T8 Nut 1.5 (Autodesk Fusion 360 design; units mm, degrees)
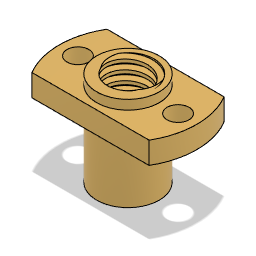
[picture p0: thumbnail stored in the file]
sketch "Sketch1" plane through (0, 0, 0) normal (0, 1, 0) x axis (1, 0, 0)
  line L1 (-11, -6) -> (11, -6)
  line L2 (-11, 6) -> (-11, -6)
  line L3 (11, 6) -> (-11, 6)
  line L4 (11, -6) -> (11, 6)
  line L5 (8, 0) -> (0, 0)
  circle C1 centre (0, 0) radius 4
  circle C2 centre (-8, 0) radius 1.75
  circle C3 centre (8, 0) radius 1.75
  arc A1 centre (0.7983, 0) radius 11.7983 clockwise from (-9.3604, -6) to (-11, 0)
  circle C4 centre (0, 0) radius 4
  arc A2 centre (-0.7983, 0) radius 11.7983 clockwise from (11, 0) to (9.3604, -6)
  arc A3 centre (0.7983, 0) radius 11.7983 clockwise from (-11, 0) to (-9.3604, 6)
  arc A4 centre (-0.7983, 0) radius 11.7983 clockwise from (9.3604, 6) to (11, 0)
  point P1 (0, 0)
  point P6 (0, 0)
  point P7 (0, 0)
  point P8 (0, 0)
  point P9 (8, 0)
  point P11 (8, 0)
  point P12 (-9.3604, -6)
  point P4 (-11, 6)
  point P5 (11, 6)
  point P3 (-11, -6)
  point P10 (-8, 0)
  horizontal L1
  perpendicular L1 L2
  parallel L1 L3
  parallel L2 L4
  coincident P1 P6
  coincident P6 P7
  coincident P1 P8
  horizontal L5
  coincident P9 P11
  tangent L2 A1
  coincident L1 P12
  dimension "d1" distance P4 P5 = 22
  dimension "d2" distance P3 P4 = 12
  dimension "d3" diameter C1 = 8
  dimension "d4" distance P8 P9 = 8
  dimension "d5" distance P9 P10 = 16
  dimension "d6" diameter C2 = 3.5
  dimension "d7" diameter C3 = 3.5
extrude "Extrude1" new body sketch "Sketch1" profile of L1 L3 C1 C2 C3 A1 C4 A2 A3 A4 along normal blind 3.5 bodies "T8 Nut 1,5"
sketch "Sketch2" plane through (0, 3.5, 0) normal (0, 1, 0) x axis (-1, 0, 0)
  line L1 (9.3604, -6) -> (-9.3604, -6)
  line L2 (-9.3604, 6) -> (9.3604, 6)
  circle C1 centre (0, 0) radius 4
  circle C2 centre (-8, 0) radius 1.75
  circle C3 centre (8, 0) radius 1.75
  arc A1 centre (0.7983, 0) radius 11.7983 clockwise from (-9.3604, -6) to (-9.3604, 6)
  arc A2 centre (-0.7983, 0) radius 11.7983 clockwise from (9.3604, 6) to (9.3604, -6)
  circle C4 centre (0, 0) radius 5
  concentric C1 C4
  dimension "d10" diameter C4 = 10
extrude "Extrude2" add sketch "Sketch2" profile of C1 C4 along normal blind 1.5
sketch "Sketch3" plane through (0, 0, 0) normal (0, -1, 0) x axis (1, 0, 0)
  line L1 (-9.3604, 6) -> (9.3604, 6)
  line L2 (9.3604, -6) -> (-9.3604, -6)
  circle C1 centre (0, 0) radius 4
  circle C2 centre (8, 0) radius 1.75
  circle C3 centre (-8, 0) radius 1.75
  arc A1 centre (-0.7983, 0) radius 11.7983 clockwise from (9.3604, 6) to (9.3604, -6)
  arc A2 centre (0.7983, 0) radius 11.7983 clockwise from (-9.3604, -6) to (-9.3604, 6)
  circle C4 centre (0, 0) radius 5
  concentric C1 C4
  dimension "d13" diameter C4 = 10
extrude "Extrude3" add sketch "Sketch3" profile of C1 C4 along normal blind 10
thread "Thread1"
component_from_bodies "Body->Comp"
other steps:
base_feature "Base Feature" bodies "T8 Nut 1,5"
create_component "CreateComponent1"
remove_body "RemoveBody1"
named bodies: "T8 Nut 1,5"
